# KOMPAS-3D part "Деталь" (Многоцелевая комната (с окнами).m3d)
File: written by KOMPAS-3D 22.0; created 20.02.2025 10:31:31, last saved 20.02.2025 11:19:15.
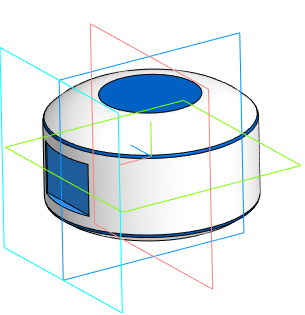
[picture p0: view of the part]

Document properties: Автор: Пользователь Windows; Полное имя файла: C:\Users\Student\Documents\Картошечка\База Сабнатика\Многоцелевая комната (с окнами).m3d

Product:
- Part/product: Деталь
    Масса: 0.415099

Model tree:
1. Эскиз:3
2. Элемент вращения:1
     Угол 1 = 360
3. Скругление:1  (with: Элемент вращения:1)
     Радиус = 1
4. Смещенная плоскость:1
     Расстояние = 25
5. Эскиз:4
6. Элемент выдавливания:1
     Расстояние 2 = 2
7. Зеркальный массив:1
8. Экземпляр ( 1 )
9. Экземпляр ( 2 )  (with: Элемент выдавливания:1)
